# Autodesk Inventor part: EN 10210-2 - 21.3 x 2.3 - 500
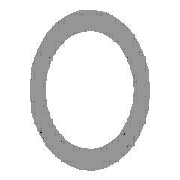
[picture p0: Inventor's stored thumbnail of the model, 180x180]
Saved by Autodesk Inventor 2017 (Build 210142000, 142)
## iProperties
Created: 2017-11
Part Number: EN 10210-2 - 21.3 x 2.3 - 500
Material: Steel, Mild
Description: Pipe
Document SubType Name: Modeling
Standard: DIN
Designer: iusti
Standard Revision: 2006-07
Standards Organization: DIN
Language: en-US
Size Designation: 21.3 x 2.3
Categories: <MemberInstance><Categories><Category DisplayName="Structural Shapes" InternalName="089c4875-fa83-4c05-b084-43b9cc11f5ed" Mnemonic="GRDR"><CategoryParameter Dis
Stock Number: 21.3 x 2.3
Density: 7.85 g/cm^3
Appearance: Semi-Polished
_CCFamilyMember: 1
_CCFamilyDisplayName: DIN EN 10210-2 - Pipe
_FrameMemberDoc: Frame Member File
_Version: 15.0.0
_GetPNFromCC: 1
IsCustomPart: 1
Author: iusti
G_L: 500.000 mm
G_W: 21.300 mm
G_H: 21.300 mm
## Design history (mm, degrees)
node "Start plane"
node "End plane"
sketch "Sketch"
  geometry: C1 r 8.35 at (0, 0); C2 r 10.65 at (0, 0); 2 further points
  constraints: 3 coincident, 2 centre point
  dimensions: "d0" = 21.3 diameter of C2 (= G_H); "d1" = 2.3 radial gap between concentric circles of C2 C1 (= G_T)
extrude "Body" new body sketch "Sketch" stored distance "d2" = 500 (= G_L); taper "d3" = 0 deg
node "Driven Length"
  sketch "Sketch3"
    geometry: L1 (0, 0)-(10, 0) reference
    constraints: 2 end point, 1 horizontal
  workplane "Work Plane3"
  sketch "Sketch4"
    geometry: L1 (-2, 0)-(12, 0) reference; L2 (-2, 500)-(12, 500) reference
    dimensions: "d7" = 500 distance between parallel lines of L1 L2 (derived)
body "Solid1"
other parameters: "G_H" = 21.3 [user parameter; used in 1 equation term], "G_T" = 2.3 [user parameter; used in 1 equation term], "G_L" = 500 (= d7) [user parameter; used in 1 equation term], "G_OFFSET_START" = 0 [user parameter; used in 1 equation term], "G_OFFSET_END" = 0 [user parameter; used in 1 equation term], "d4" = 0 (computed from G_OFFSET_START), "d6" = 90 deg
